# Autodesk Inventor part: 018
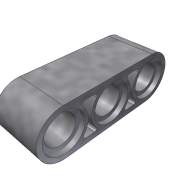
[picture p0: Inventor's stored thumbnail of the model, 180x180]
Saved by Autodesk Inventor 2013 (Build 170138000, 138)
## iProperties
Created: 2013-03
Part Number: 018
Material: Generic
Document SubType Name: Modeling
Designer: perblt
Density: 1 g/cm^3
Author: perblt
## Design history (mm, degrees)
sketch "Sketch2" dims "d95" = 10
  geometry: L1 (-24.8, 0)-(8.8, 0) reference; L2 (-16, 4)-(0, 4); L3 (-4, -4)-(-4, -3.79); L4 (0, -4)-(-0.571, -4); L5 (-0.571, -4)-(-16, -4); C1 r 3.2 at (0, 0); C2 r 3.2 at (-8, 0); C3 r 3.2 at (-16, 0); A1 r 4 centre (0, 0) between (0, -4) and (0, 4); A2 r 4 centre (-16, 0) between (-16, 4) and (-16, -4); 1 further point
  constraints: 8 end point, 5 centre point, 4 point on circle, 3 coincident, 3 tangent, 1 horizontal, 1 parallel, 4 other
  dimensions: "d" = 6.4 diameter of C1; "d24" = 4 radius of A1; "d92" = 8 distance of C1.centre C2.centre
extrude "Extrusion6" new body sketch "Sketch2" stored distance "d98" = 8; taper "d99" = 0 deg
sketch "Sketch4"
  geometry: L1 (32, -4)-(0, -4); L2 (28.83, -3)-(27.17, -3); L3 (27.17, 3)-(28.83, 3); L4 (20.83, -3)-(19.17, -3); L5 (19.17, 3)-(20.83, 3); L6 (12.83, -3)-(11.17, -3); L7 (11.17, 3)-(12.83, 3); L8 (4.83, -3)-(3.17, -3); L9 (3.17, 3)-(4.83, 3); L10 (-3.17, -3)-(-4.83, -3); L11 (-4.83, 3)-(-3.17, 3); L12 (-11.17, -3)-(-12.83, -3); L13 (-12.83, 3)-(-11.17, 3); L14 (-19.17, -3)-(-20.83, -3); L15 (-20.83, 3)-(-19.17, 3); L16 (-27.17, -3)-(-28.83, -3); L17 (-28.83, 3)-(-27.17, 3); L18 (-35.17, -3)-(-36.83, -3); L19 (-36.83, 3)-(-35.17, 3); L20 (-43.17, -3)-(-44.83, -3); L21 (-44.83, 3)-(-43.17, 3); A1 r 3.7 centre (32, 0) between (29.139, 2.346) and (29.139, -2.346); A2 r 3.7 centre (24, 0) between (26.861, -2.346) and (26.861, 2.346); A3 r 0.4 centre (27.17, -2.6) between (26.861, -2.346) and (27.17, -3); A4 r 0.4 centre (28.83, -2.6) between (28.83, -3) and (29.139, -2.346); A5 r 0.4 centre (27.17, 2.6) between (27.17, 3) and (26.861, 2.346); A6 r 0.4 centre (28.83, 2.6) between (29.139, 2.346) and (28.83, 3); A7 r 0.4 centre (20.83, -2.6) between (20.83, -3) and (21.139, -2.346); A8 r 0.4 centre (19.17, -2.6) between (18.861, -2.346) and (19.17, -3); A9 r 3.7 centre (24, 0) between (21.139, 2.346) and (21.139, -2.346); A10 r 3.7 centre (16, 0) between (18.861, -2.346) and (18.861, 2.346); A11 r 0.4 centre (20.83, 2.6) between (21.139, 2.346) and (20.83, 3); A12 r 0.4 centre (19.17, 2.6) between (19.17, 3) and (18.861, 2.346); A13 r 0.4 centre (12.83, -2.6) between (12.83, -3) and (13.139, -2.346); A14 r 0.4 centre (11.17, -2.6) between (10.861, -2.346) and (11.17, -3); A15 r 3.7 centre (16, 0) between (13.139, 2.346) and (13.139, -2.346); A16 r 3.7 centre (8, 0) between (10.861, -2.346) and (10.861, 2.346); A17 r 0.4 centre (12.83, 2.6) between (13.139, 2.346) and (12.83, 3); A18 r 0.4 centre (11.17, 2.6) between (11.17, 3) and (10.861, 2.346); A19 r 0.4 centre (4.83, -2.6) between (4.83, -3) and (5.139, -2.346); A20 r 0.4 centre (3.17, -2.6) between (2.861, -2.346) and (3.17, -3); A21 r 3.7 centre (8, 0) between (5.139, 2.346) and (5.139, -2.346); A22 r 3.7 centre (0, 0) between (2.861, -2.346) and (2.861, 2.346); A23 r 0.4 centre (4.83, 2.6) between (5.139, 2.346) and (4.83, 3); A24 r 0.4 centre (3.17, 2.6) between (3.17, 3) and (2.861, 2.346); A25 r 0.4 centre (-3.17, -2.6) between (-3.17, -3) and (-2.861, -2.346); A26 r 0.4 centre (-4.83, -2.6) between (-5.139, -2.346) and (-4.83, -3); A27 r 3.7 centre (0, 0) between (-2.861, 2.346) and (-2.861, -2.346); A28 r 3.7 centre (-8, 0) between (-5.139, -2.346) and (-5.139, 2.346); A29 r 0.4 centre (-3.17, 2.6) between (-2.861, 2.346) and (-3.17, 3); A30 r 0.4 centre (-4.83, 2.6) between (-4.83, 3) and (-5.139, 2.346); A31 r 0.4 centre (-11.17, -2.6) between (-11.17, -3) and (-10.861, -2.346); A32 r 0.4 centre (-12.83, -2.6) between (-13.139, -2.346) and (-12.83, -3); A33 r 3.7 centre (-8, 0) between (-10.861, 2.346) and (-10.861, -2.346); A34 r 3.7 centre (-16, 0) between (-13.139, -2.346) and (-13.139, 2.346); A35 r 0.4 centre (-11.17, 2.6) between (-10.861, 2.346) and (-11.17, 3); A36 r 0.4 centre (-12.83, 2.6) between (-12.83, 3) and (-13.139, 2.346); A37 r 0.4 centre (-19.17, -2.6) between (-19.17, -3) and (-18.861, -2.346); A38 r 0.4 centre (-20.83, -2.6) between (-21.139, -2.346) and (-20.83, -3); A39 r 3.7 centre (-16, 0) between (-18.861, 2.346) and (-18.861, -2.346); A40 r 3.7 centre (-24, 0) between (-21.139, -2.346) and (-21.139, 2.346); A41 r 0.4 centre (-19.17, 2.6) between (-18.861, 2.346) and (-19.17, 3); A42 r 0.4 centre (-20.83, 2.6) between (-20.83, 3) and (-21.139, 2.346); A43 r 0.4 centre (-27.17, -2.6) between (-27.17, -3) and (-26.861, -2.346); A44 r 0.4 centre (-28.83, -2.6) between (-29.139, -2.346) and (-28.83, -3); A45 r 3.7 centre (-24, 0) between (-26.861, 2.346) and (-26.861, -2.346); A46 r 3.7 centre (-32, 0) between (-29.139, -2.346) and (-29.139, 2.346); A47 r 0.4 centre (-27.17, 2.6) between (-26.861, 2.346) and (-27.17, 3); A48 r 0.4 centre (-28.83, 2.6) between (-28.83, 3) and (-29.139, 2.346); A49 r 0.4 centre (-35.17, -2.6) between (-35.17, -3) and (-34.861, -2.346); A50 r 0.4 centre (-36.83, -2.6) between (-37.139, -2.346) and (-36.83, -3); A51 r 3.7 centre (-32, 0) between (-34.861, 2.346) and (-34.861, -2.346); A52 r 3.7 centre (-40, 0) between (-37.139, -2.346) and (-37.139, 2.346); A53 r 0.4 centre (-35.17, 2.6) between (-34.861, 2.346) and (-35.17, 3); A54 r 0.4 centre (-36.83, 2.6) between (-36.83, 3) and (-37.139, 2.346); A55 r 0.4 centre (-43.17, -2.6) between (-43.17, -3) and (-42.861, -2.346); A56 r 0.4 centre (-44.83, -2.6) between (-45.139, -2.346) and (-44.83, -3); A57 r 3.7 centre (-40, 0) between (-42.861, 2.346) and (-42.861, -2.346); A58 r 3.7 centre (-48, 0) between (-45.139, -2.346) and (-45.139, 2.346); A59 r 0.4 centre (-43.17, 2.6) between (-42.861, 2.346) and (-43.17, 3); A60 r 0.4 centre (-44.83, 2.6) between (-44.83, 3) and (-45.139, 2.346); 1 further point
  constraints: 120 point on circle, 60 centre point, 42 end point, 8 tangent, 1 horizontal, 1 parallel, 198 other
  dimensions: "d45" = 7.4 diameter of A1; "d46" = 7.4 diameter of A2; "d49" = 0.8 diameter of A3; "d50" = 0.8 diameter of A4; "d51" = 0.8 diameter of A5; "d52" = 0.8 diameter of A6; "d57" = 8 distance of A1.end A7.end
extrude "Extrusion8" cut sketch "Sketch4" stored distance "d120" = 50; taper "d121" = 0 deg
sketch "Sketch3" dims "d41" = 10, "d105" = 10
  geometry: L1 (0, -4.752)-(0, 4.752) reference; L2 (-68.752, 0)-(52.752, 0) reference; C1 r 2.4 at (0, 0); C2 r 3.394 at (0, 0); C3 r 2.4 at (8, 0); C4 r 3.394 at (8, 0); C5 r 2.4 at (16, 0); C6 r 3.394 at (16, 0); C7 r 2.4 at (24, 0); C8 r 3.394 at (24, 0); C9 r 2.4 at (32, 0); C10 r 3.394 at (32, 0); C11 r 2.4 at (-8, 0); C12 r 3.394 at (-8, 0); C13 r 2.4 at (-16, 0); C14 r 3.394 at (-16, 0); C15 r 2.4 at (-24, 0); C16 r 3.394 at (-24, 0); C17 r 2.4 at (-32, 0); C18 r 3.394 at (-32, 0); C19 r 2.4 at (-40, 0); C20 r 3.394 at (-40, 0); C21 r 2.4 at (-48, 0); C22 r 3.394 at (-48, 0); 7 further points
  constraints: 22 centre point, 18 coincident, 2 horizontal, 46 other
  dimensions: "d28" = 4.8 diameter of C1; "d38" = 8 distance of C1.centre C3.centre; "d102" = 8 distance of point (0, 0) point (-8, 0)
extrude "Extrusion2" new body sketch "Sketch3" stored distance "d43" = 6.4; taper "d44" = 0 deg
sketch "Sketch5" dims "d82" = 10
  geometry: L1 (26.635, 3.313)-(29.368, 3.313); L2 (29.368, 3.313)-(29.368, -3.607); L3 (29.368, -3.607)-(26.635, -3.607); L4 (26.635, -3.607)-(26.635, 3.313); L5 (4, 4)-(32, 4); L6 (18.635, 3.313)-(21.368, 3.313); L7 (21.368, 3.313)-(21.368, -3.607); L8 (21.368, -3.607)-(18.635, -3.607); L9 (18.635, -3.607)-(18.635, 3.313); L10 (10.635, 3.313)-(13.368, 3.313); L11 (13.368, 3.313)-(13.368, -3.607); L12 (13.368, -3.607)-(10.635, -3.607); L13 (10.635, -3.607)-(10.635, 3.313); L14 (2.635, 3.313)-(5.368, 3.313); L15 (5.368, 3.313)-(5.368, -3.607); L16 (5.368, -3.607)-(2.635, -3.607); L17 (2.635, -3.607)-(2.635, 3.313); L18 (-5.365, 3.313)-(-2.632, 3.313); L19 (-2.632, 3.313)-(-2.632, -3.607); L20 (-2.632, -3.607)-(-5.365, -3.607); L21 (-5.365, -3.607)-(-5.365, 3.313); L22 (-13.365, 3.313)-(-10.632, 3.313); L23 (-10.632, 3.313)-(-10.632, -3.607); L24 (-10.632, -3.607)-(-13.365, -3.607); L25 (-13.365, -3.607)-(-13.365, 3.313); L26 (-21.365, 3.313)-(-18.632, 3.313); L27 (-18.632, 3.313)-(-18.632, -3.607); L28 (-18.632, -3.607)-(-21.365, -3.607); L29 (-21.365, -3.607)-(-21.365, 3.313); L30 (-29.365, 3.313)-(-26.632, 3.313); L31 (-26.632, 3.313)-(-26.632, -3.607); L32 (-26.632, -3.607)-(-29.365, -3.607); L33 (-29.365, -3.607)-(-29.365, 3.313); L34 (-37.365, 3.313)-(-34.632, 3.313); L35 (-34.632, 3.313)-(-34.632, -3.607); L36 (-34.632, -3.607)-(-37.365, -3.607); L37 (-37.365, -3.607)-(-37.365, 3.313); L38 (-45.365, 3.313)-(-42.632, 3.313); L39 (-42.632, 3.313)-(-42.632, -3.607); L40 (-42.632, -3.607)-(-45.365, -3.607); L41 (-45.365, -3.607)-(-45.365, 3.313)
  constraints: 82 end point, 2 horizontal, 2 parallel, 1 perpendicular, 72 other
  dimensions: "d79" = 8 distance of L1.start L6.start
extrude "Extrusion4" join sketch "Sketch5" stored distance "d84" = 1.6; taper "d85" = 0 deg
body "Solid1"
body "Solid2"
other parameters: "d0" = 4.8, "d47" = 1, "d48" = 1, "d63" = 7.4, "d64" = 1, "d65" = 1
